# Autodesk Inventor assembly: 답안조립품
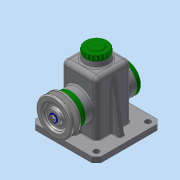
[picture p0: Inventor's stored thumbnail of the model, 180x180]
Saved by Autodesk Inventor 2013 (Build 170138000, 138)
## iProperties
Created: 2018-10
Part Number: 답안조립품
Document SubType Name: Assembly
Designer: Administrator
Author: Administrator
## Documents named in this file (14)
- C:\Users\Administrator\Desktop\481013V1015\답안조립품.iam
- C:\Users\Administrator\Desktop\481013V1015\본체.ipt
- C:\Users\Administrator\Desktop\481013V1015\V-벨트풀리.ipt
- C:\Users\Administrator\Desktop\481013V1015\뒤커버.ipt
- C:\Users\Administrator\Desktop\481013V1015\멈춤링 15 x 1.ipt
- C:\Users\Administrator\Desktop\481013V1015\베어링 15 x 35 x 11.ipt
- C:\Users\Administrator\Desktop\481013V1015\볼트 M4 x 10.ipt
- C:\Users\Administrator\Desktop\481013V1015\볼트 M6 x 12.ipt
- C:\Users\Administrator\Desktop\481013V1015\상부캡.ipt
- C:\Users\Administrator\Desktop\481013V1015\앞커버.ipt
- C:\Users\Administrator\Desktop\481013V1015\오일실 15 25 7.ipt
- C:\Users\Administrator\Desktop\481013V1015\와셔.ipt
- C:\Users\Administrator\Desktop\481013V1015\축.ipt
- C:\Users\Administrator\Desktop\481013V1015\키 5 x 5 x 14.ipt
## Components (1 placed, 1 different names)
1. V-벨트풀리:1 — 플러쉬:1
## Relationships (1: Flush 1)
- 플러쉬:1 [Flush]: V-벨트풀리:1
